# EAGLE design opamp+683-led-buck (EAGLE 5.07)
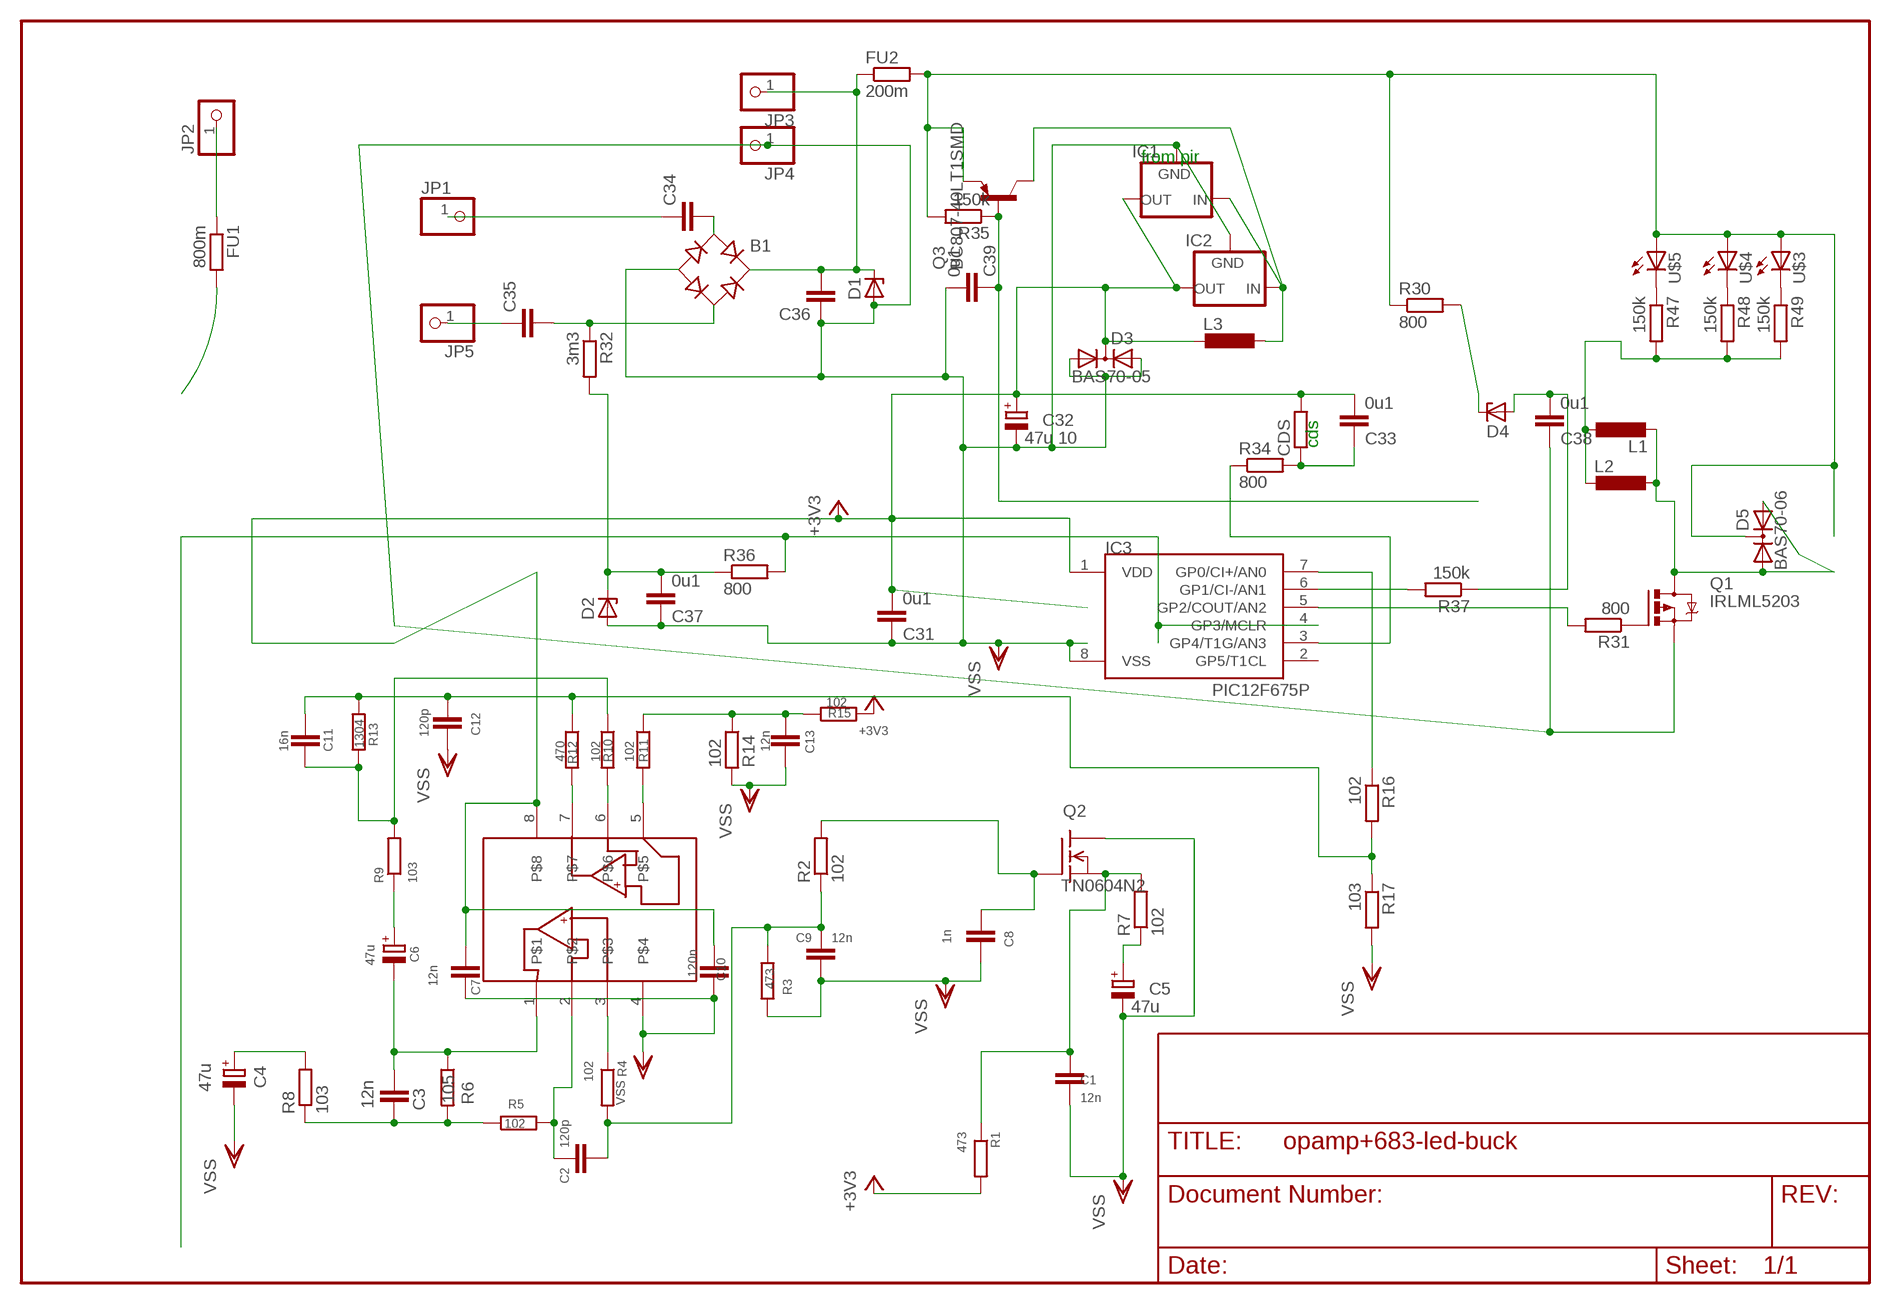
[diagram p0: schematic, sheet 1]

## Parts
B1  RB1A  [RB1A]
C1  12n  C-EUC0805  [C0805]
C2  120p  C-EUC0805  [C0805]
C3  12n  C-EUC0805  [C0805]
C4  47u  CPOL-EUE2.5-5  [E2,5-5]
C5  47u  CPOL-EUE2.5-5  [E2,5-5]
C6  47u  CPOL-EUE2.5-5  [E2,5-5]
C7  12n  C-EUC0805  [C0805]
C8  1n  C-EUC0805  [C0805]
C9  12n  C-EUC0805  [C0805]
C10  120n  C-EUC0805  [C0805]
C11  16n  C-EUC0805  [C0805]
C12  120p  C-EUC0805  [C0805]
C13  12n  C-EUC0805  [C0805]
C31  0u1  C-EUC1206  [C1206]
C32  47u 10  CPOL-EUE2.5-5  [E2,5-5]
C33  0u1  C-EUC1206  [C1206]
C34  C-EU050-025X075  [C050-025X075]
C35  C-EU050-025X075  [C050-025X075]
C36  C-EU050-025X075  [C050-025X075]
C37  0u1  C-EUC0805  [C0805]
C38  0u1  C-EUC0805  [C0805]
C39  0u1  C-EUC1206  [C1206]
CDS  R-EU_0207/5V  [0207/5V]
D1  ZENER-DIODEZD-7.5  [ZDIO-7.5]
D2  ZENER-DIODESOT23  [SOT23]
D3  BAS70-05  [SOT23]
D4  ZENER-DIODESOT23  [SOT23]
D5  BAS70-06  [SOT23]
FU1  800m  R-EU_0204/5  [0204/5]
FU2  200m  R-EU_0204/5  [0204/5]
IC1  XC63FPT  [TO92]
IC2  XC63FPP  [SOT89R]
IC3  PIC12F675P  [DIL8]
JP1  PINHD-1X1  [1X01]
JP2  PINHD-1X1  [1X01]
JP3  PINHD-1X1  [1X01]
JP4  PINHD-1X1  [1X01]
JP5  PINHD-1X1  [1X01]
L1  L-EUL5650M  [L5650M]
L2  L-EU0207/7  [0207/7]
L3  L-EU0204V  [0204V]
Q1  IRLML5203  [MICRO3]
Q2  TN0604N2  [TO-39]
Q3  BC807-40LT1SMD  [SOT23-BEC]
R1  473  R-EU_R0805  [R0805]
R2  102  R-EU_R0805  [R0805]
R3  473  R-EU_R0805  [R0805]
R4  102  R-EU_R0805  [R0805]
R5  102  R-EU_R0805  [R0805]
R6  105  R-EU_R0805  [R0805]
R7  102  R-EU_R0805  [R0805]
R8  103  R-EU_R0805  [R0805]
R9  103  R-EU_R0805  [R0805]
R10  102  R-EU_R0805  [R0805]
R11  102  R-EU_R0805  [R0805]
R12  470  R-EU_R0805  [R0805]
R13  1304  R-EU_R0805  [R0805]
R14  102  R-EU_R0805  [R0805]
R15  102  R-EU_R0805  [R0805]
R16  102  R-EU_R0805  [R0805]
R17  103  R-EU_R1206  [R1206]
R30  800  R-EU_R0805  [R0805]
R31  800  R-EU_R0805  [R0805]
R32  3m3  R-EU_R1206  [R1206]
R34  800  R-EU_0617/22  [0617/22]
R35  150k  R-EU_R0805  [R0805]
R36  800  R-EU_R0805  [R0805]
R37  150k  R-EU_0207/12  [0207/12]
R47  150k  R-EU_R1206  [R1206]
R48  150k  R-EU_R1206  [R1206]
R49  150k  R-EU_R1206  [R1206]
U$1  MCP6042SOIC  [SO-08]
U$3  LED5MM  [LED5MM]
U$4  LED5MM  [LED5MM]
U$5  LED5MM  [LED5MM]

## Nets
+3V3: C7.1 C10.1 C31.2 C32.+ C33.2 CDS.2 D3.3(C) IC1.3(OUT) IC2.3(OUT) IC3.1(VDD) L3.2 R1.2 R15.2 U$1.8
N$1: B1.+ C36.2 D1.C FU2.1 JP3.1
N$4: FU1.1 JP2.1
N$6: D4.3(C) R30.2
N$7: D5.3(C) FU2.2 Q3.E R30.1 R35.2 U$3.A U$4.A U$5.A
N$8: C39.1 Q3.B R35.1
N$9: FU1.2
N$10: Q1.1(G) R31.1
N$11: C5.+ R7.1
N$12: IC3.4(GP3/MCLR) R36.2
N$13: IC3.6(GP1/CI-/AN1) R37.2
N$14: IC3.5(GP2/COUT/AN2) R31.2
N$15: IC1.2(IN) IC2.2(IN) L3.1 Q3.C
N$16: C37.2 D2.3(C) R32.2 R36.1
N$17: C35.1 JP5.1
N$18: B1.AC2 C35.2 R32.1
N$19: R4.1 U$1.3
N$20: C34.1 JP1.1
N$21: IC3.3(GP4/T1G/AN3) R34.1
N$22: L1.1 L2.2 R47.2 R48.2 R49.2
N$23: C33.1 CDS.1 R34.2
N$24: C2.1 R5.2 U$1.2
N$25: C3.2 R5.1 R6.2 R8.1
N$26: D5.1(A1) D5.2(A2) L1.2 L2.1 Q1.3(D)
N$27: C4.+ R8.2
N$28: C11.2 R9.2 R10.1 R13.2
N$29: IC3.7(GP0/CI+/AN0) R16.1
N$30: C3.1 C6.- R6.1 U$1.1
N$31: R10.2 U$1.6
N$32: C11.1 C12.2 R12.1 R13.1 R16.2 R17.1
N$33: B1.AC1 C34.2
N$34: C38.2 D4.1(A) R37.1
N$35: C6.+ R9.1
N$36: R12.2 U$1.7
N$38: R47.1 U$5.K(C)
N$39: R11.2 U$1.5
N$40: C13.1 R11.1 R14.1 R15.1
N$42: C1.1 Q2.1(S) R1.1 R7.2
N$46: C8.1 Q2.2(G) R2.2
N$52: C2.2 C9.1 R2.1 R3.1 R4.2
N$54: R48.1 U$4.K(C)
N$55: R49.1 U$3.K(C)
VSS: B1.- C1.2 C4.- C5.- C7.2 C8.2 C9.2 C10.2 C12.1 C13.2 C31.1 C32.- C36.1 C37.1 C38.1 C39.2 D1.A D2.1(A) D3.1(A1) D3.2(A2) IC1.1(GND) IC2.1(GND) IC3.8(VSS) JP4.1 Q1.2(S) Q2.3(D) R3.2 R14.2 R17.2 U$1.4
Unconnected: IC3.2(GP5/T1CL)

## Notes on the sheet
- from pir
- cds

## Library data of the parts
B1 = rectifier:RB1A: RECTIFIER 1 A
C1-C3 C7-C13 = rcl-2:C-EU: CAPACITOR, European symbol
C4-C6 C32 = rcl:CPOL-EU: POLARIZED CAPACITOR, European symbol
C31 C33-C39 = rcl:C-EU: CAPACITOR, European symbol
CDS = rcl(2):R-EU_: RESISTOR, European symbol
D1 D2 D4 = diode-1:ZENER-DIODE: Z-Diode
D3 = diode-1:BAS70-05: Silicon Schottky Diodes General-purpose diode for high-speed switching
D5 = diode-1:BAS70-06: Silicon Schottky Diodes General-purpose diode for high-speed switching
FU1 FU2 R30-R32 R34-R37 R47-R49 = rcl:R-EU_: RESISTOR, European symbol
IC1 IC2 = v-reg:XC63FP: Positiv Voltage Regulators www.torex.co.jp/english/product/pro02/pdf/0201_xc62fp.pdf
IC3 = microchip-3:PIC12F6*: uPC nW 1k Program Flash memory 2x Timer Comparator 10b A/D converter/ 4xIN
JP1-JP5 = pinhead:PINHD-1X1: PIN HEADER
L1 = rcl-2:L-EU: INDUCTOR, European symbol
L2 L3 = rcl:L-EU: INDUCTOR, European symbol
Q1 = transistor-power:IRLML5203: HEXFET P-Channel Power MOSFET
Q2 = transistor-fet:TN0604N2: N-Channel Enhancement MOSFET 40V; 4A; 0,85Ohm
Q3 = transistor-pnp:BC807*: PNP Transistror
R1-R17 = rcl-2:R-EU_: RESISTOR, European symbol
U$1 = microchip-3:MCP6042
U$3-U$5 = led(3):LED: LED

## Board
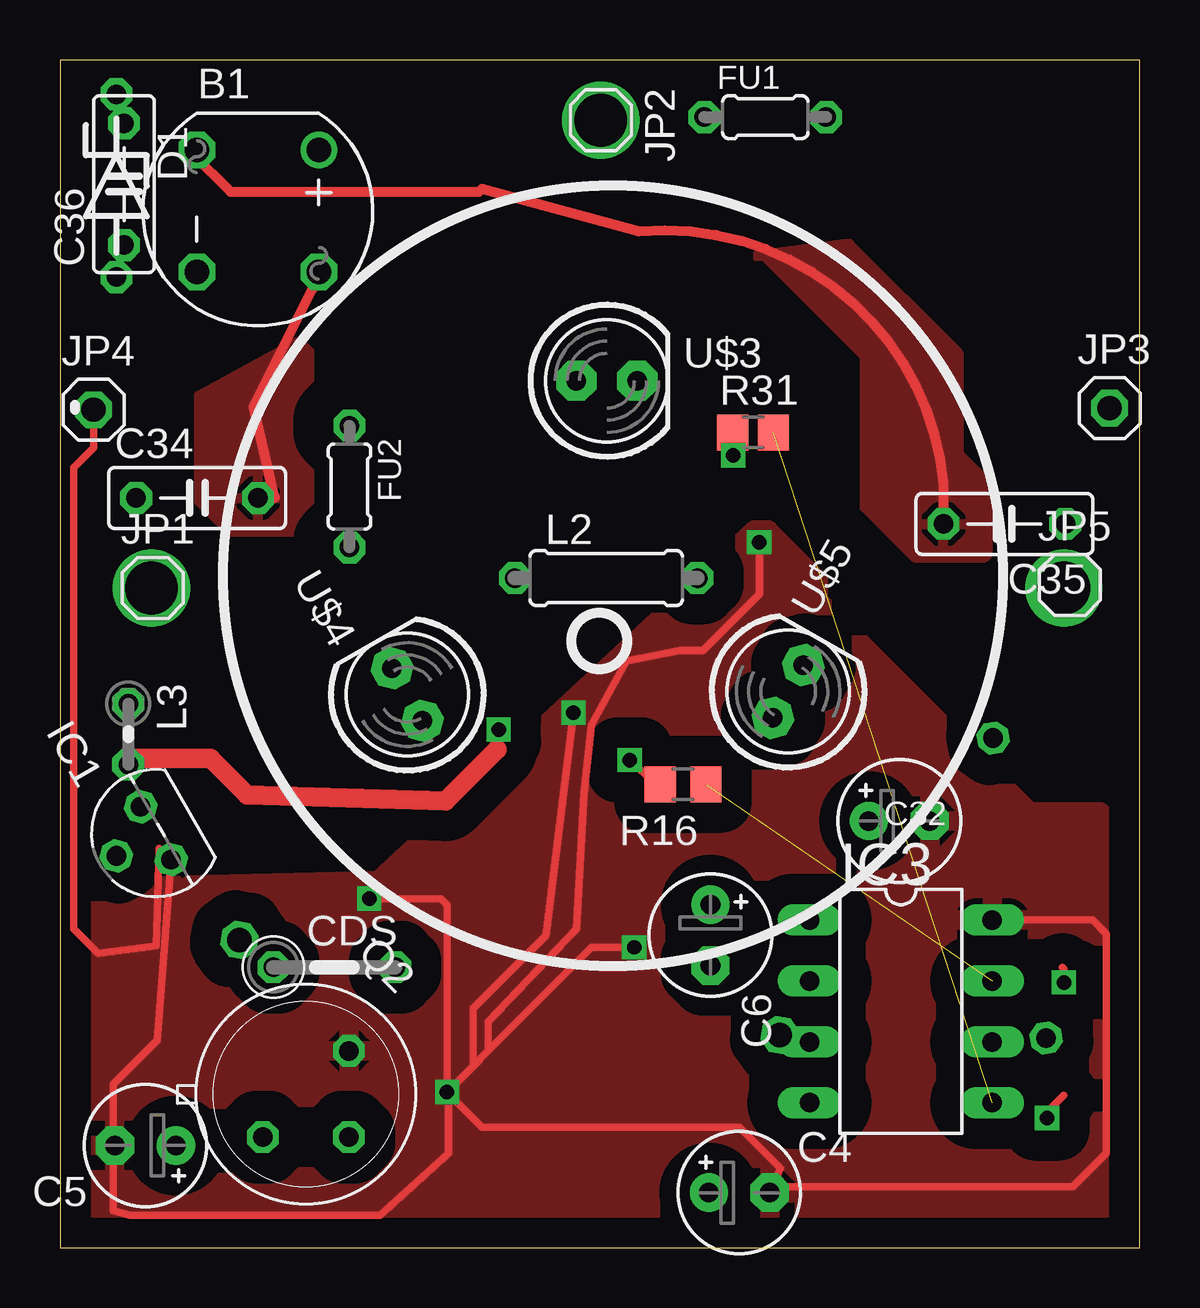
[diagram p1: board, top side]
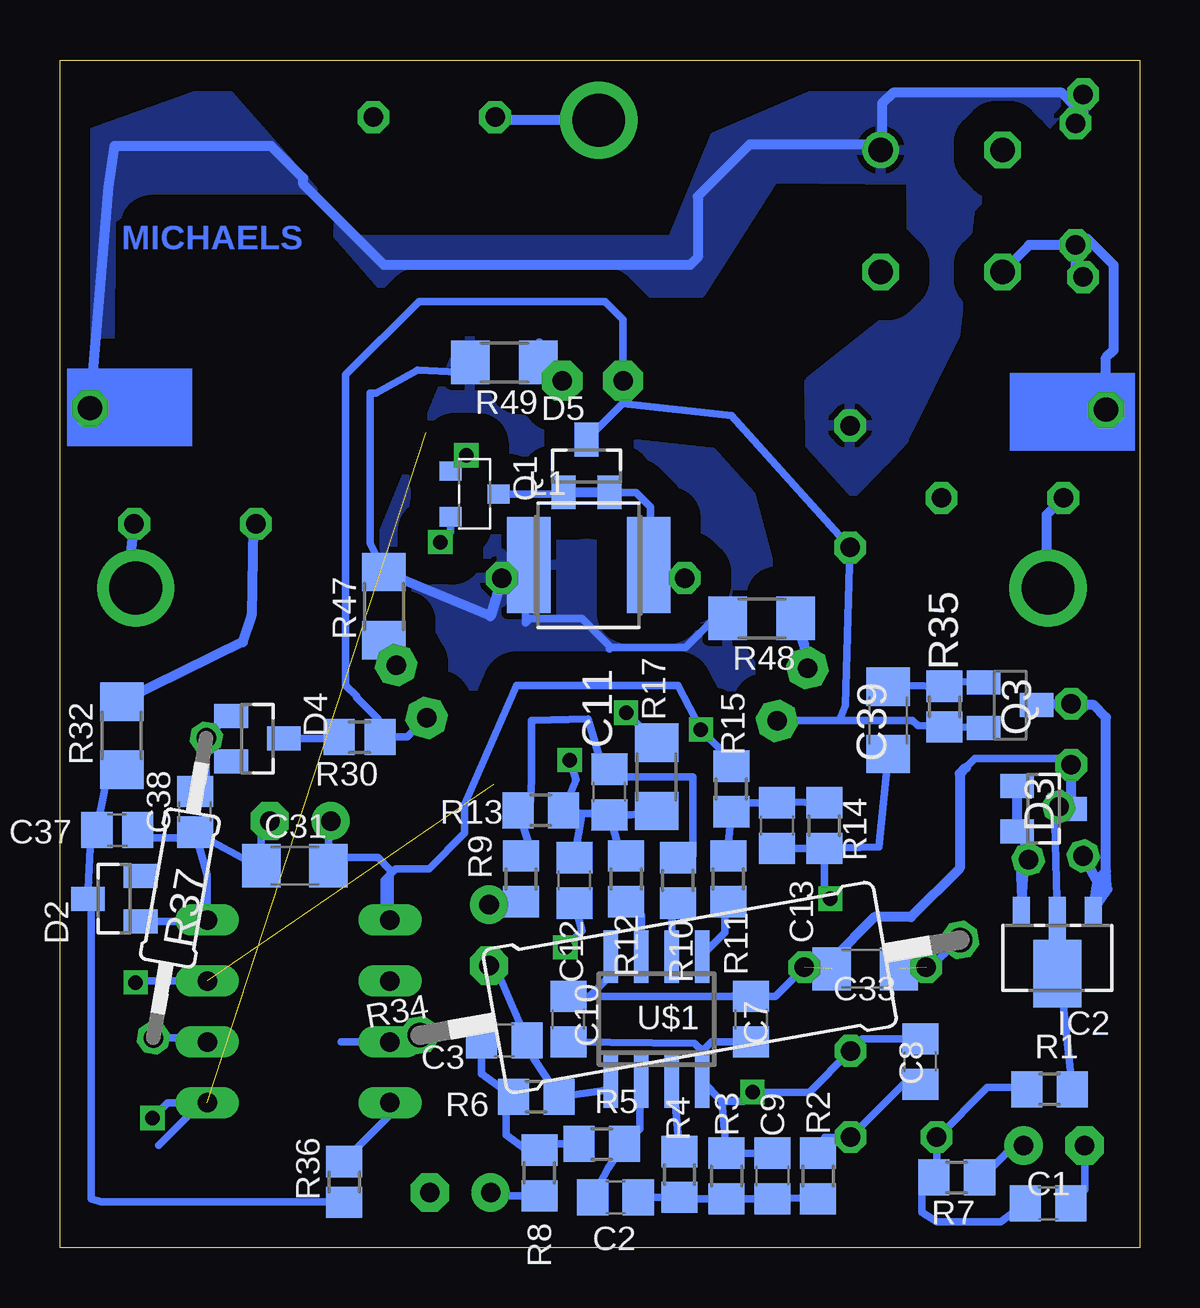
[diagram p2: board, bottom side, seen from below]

Size 45 x 49.5 mm. Coordinates in mm from the lower left corner, seen from the top.
Outline: 0,0 45,0 45,49.5 0,49.5 0,0
Copper layers (1*16): Top 0.035mm / dielectric 1.5mm / Bottom 0.035mm
Design rules "default": minimum track width 10mil, minimum drill 24mil, track to track 8mil, track to pad 8mil, pad to pad 8mil, via to via 8mil, smd to smd 8mil, copper to edge 40mil, drill to drill 8mil, minimum pad ring 10mil, minimum via ring 8mil, stop-mask expansion 4mil, vias tented up to drill 0mil, thermal gap 10mil

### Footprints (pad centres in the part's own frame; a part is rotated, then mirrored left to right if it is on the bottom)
RB1A = drill 1.016 round: + -2.54,2.54 | drill 1.016 octagon: - 2.54,-2.54; AC1 2.54,2.54; AC2 -2.54,-2.54
C0805 = smd 1.3 x 1.5: 1 -0.95,0; 2 0.95,0
E2,5-5 = drill 0.813 pad 1.6 round: + -1.27,0 | drill 0.813 pad 1.6 octagon: - 1.27,0
C1206 = smd 1.6 x 1.8: 1 -1.4,0; 2 1.4,0
C050-025X075 = drill 0.813 octagon: 1 -2.54,0; 2 2.54,0
C0805' = smd 1.3 x 1.5: 1 -0.85,0; 2 0.85,0
0207/5V = drill 0.813 octagon: 1 -2.54,0; 2 2.54,0
ZDIO-7.5 = drill 0.813 octagon: A 3.81,0; C -3.81,0
SOT23 = smd 1 x 1.4: 1 -0.95,-1.1; 2 0.95,-1.1; 3 0,1.1
0204/5 = drill 0.813 octagon: 1 -2.54,0; 2 2.54,0
TO92 = drill 0.813 octagon: 1 -1.27,0; 2 0,1.905; 3 1.27,0
SOT89R = smd 0.7 x 1.1: 1 1.5,-1.75; 2 -1.5,-1.75 | smd 0.7 x 1.8: 3 0,-1.4 | smd 2 x 2.8: 4 0,0.9
DIL8 = drill 0.813 long: 1 -3.81,-3.81; 2 -1.27,-3.81; 3 1.27,-3.81; 4 3.81,-3.81; 5 3.81,3.81; 6 1.27,3.81; 7 -1.27,3.81; 8 -3.81,3.81
1X01 = drill 1.016 octagon: 1 0,0
L5650M = smd 1.8 x 4: 1 -2.5,0; 2 2.5,0
0207/7 = drill 0.813 octagon: 1 -3.81,0; 2 3.81,0
0204V = drill 0.813 octagon: 1 -1.27,0; 2 1.27,0
MICRO3 = smd 0.8 x 0.9: 1 -0.95,-1; 2 0.95,-1; 3 0,1
TO-39 = drill 0.813 octagon: 1 0,-2.54; 2 2.54,0; 3 0,2.54
SOT23-BEC = smd 1 x 1.4: B -0.95,-1.1; C 0,1.1; E 0.95,-1.1
R0805 = smd 1.3 x 1.5: 1 -0.95,0; 2 0.95,0
R1206 = smd 1.6 x 1.803: 1 -1.422,0; 2 1.422,0
R0805' = smd 1.3 x 1.5: 1 -0.85,0; 2 0.85,0
0617/22 = drill 1.016 octagon: 1 -11.43,0; 2 11.43,0
0207/12 = drill 0.813 octagon: 1 -6.35,0; 2 6.35,0
SO-08 = smd 0.6 x 2.2: 1 -1.905,-2.6; 2 -0.635,-2.6; 3 0.635,-2.6; 4 1.905,-2.6; 5 1.905,2.6; 6 0.635,2.6; 7 -0.635,2.6; 8 -1.905,2.6
LED5MM = drill 0.813 pad 1.676 octagon: A -1.27,0; K 1.27,0

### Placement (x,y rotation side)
B1  8.25,43.21 270 top
C1  3.81,1.84 0 bottom
C2  21.84,2.1 0 bottom
C3  26.48,8.64 180 bottom
C4  28.32,2.29 0 top
C5  3.56,4.25 180 top
C6  27.11,13.02 270 top
C7  16.19,9.53 270 bottom
C8  9.14,7.75 90 bottom
C9  15.3,2.98 90 bottom
C10  23.81,9.53 270 bottom
C11  22.1,18.99 90 bottom
C12  23.56,15.3 90 bottom
C13  15.11,17.59 270 bottom
C31  35.21,15.92 0 bottom
C32  34.99,17.78 0 top
C33  11.43,11.62 180 bottom
C34  5.71,31.24 0 top
C35  39.37,30.16 180 top
C36  2.67,44.32 90 top
C37  0u1  [C0805']  42.61,17.4 180 bottom
C38  0u1  [C0805']  39.37,18.16 90 bottom
C39  10.48,21.97 270 bottom
CDS  11.43,11.68 0 top
D1  2.35,44.26 270 top
D2  42.74,14.54 90 bottom
D3  4,18.29 270 bottom
D4  36.77,21.21 270 bottom
D5  23.05,32.58 0 bottom
FU1  29.4,47.12 0 top
FU2  12.07,31.72 270 top
IC1  4,17.28 120 top
IC2  3.43,12.32 180 bottom
IC3  35.05,9.84 270 top
JP1  3.87,27.5 0 top
JP2  22.54,46.99 270 top
JP3  43.75,34.99 0 top
JP4  1.4,34.92 0 top
JP5  42.1,27.62 0 top
L1  22.96,28.44 0 bottom
L2  22.77,27.91 0 top
L3  2.85,21.4 270 top
Q1  27.72,31.41 270 bottom
Q2  10.25,6.4 315 top
Q3  5.4,22.61 270 bottom
R1  3.75,6.6 0 bottom
R2  13.4,2.98 90 bottom
R3  17.21,2.98 90 bottom
R4  19.18,3.05 270 bottom
R5  22.42,4.32 0 bottom
R6  25.15,6.29 180 bottom
R7  7.62,2.92 180 bottom
R8  25.02,3.11 270 bottom
R9  25.78,15.37 90 bottom
R10  19.24,15.3 270 bottom
R11  17.14,15.37 270 bottom
R12  21.4,15.37 270 bottom
R13  24.96,18.22 180 bottom
R14  13.14,17.59 270 bottom
R15  17.02,19.11 90 bottom
R16  25.97,19.3 180 top
R17  20.13,19.62 90 bottom
R30  800  [R0805']  32.51,21.27 180 bottom
R31  800  [R0805']  28.89,33.97 0 top
R32  42.42,21.34 270 bottom
R34  18.74,10.84 10 bottom
R35  150k  [R0805']  8.13,22.54 270 bottom
R36  800  [R0805']  33.15,2.73 90 bottom
R37  40.01,14.99 260 bottom
R47  31.5,26.73 90 bottom
R48  15.75,26.23 180 bottom
R49  26.48,36.89 180 bottom
U$1  20.13,9.53 0 bottom
U$3  22.8,36.13 0 top
U$4  14.48,23.05 120 top
U$5  30.35,23.18 60 top

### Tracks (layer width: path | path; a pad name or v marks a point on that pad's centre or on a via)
+3V3  (via drill 0.6)  (1 unrouted)
  Top 0.305: 18.22,20.77 v18.29,21.59 | L3.2 3.1,20.38
  Top 0.813: 18.22,20.77 16.07,18.61 7.81,18.86 6.29,20.38 3.1,20.38
  Bottom 0.305: 22.92,10.47 C7.1 15.18,10.47 CDS.2 | 22.92,10.47 C10.1 | U$1.8 22.04,11.36 22.92,10.47 | 7.24,20 6.86,20.38 3.1,20.38 L3.2 | C32.+ 33.81,17.69 C31.2 33.47,16.26 31.75,16.26 31.24,15.75 IC3.1 31.5,13.91 31.5,15.3 31.01,15.79 29.62,15.79 28.13,17.27 28.13,18.48 25.97,23.43 19.24,23.43 v18.29,21.59 17.53,20.83 R15.2 | R1.2 3.43,12.45 IC2.3 3.56,18.48 | 3.56,18.48 2.98,18.56 IC1.3 | D3.3 2.92,18.29 3.56,18.48
  Bottom 0.406: L3.2 2.85,18.09 D3.3 | C33.2 12.83,12 11.05,13.78 9.53,13.78 7.49,15.81 7.49,19.75 7.24,20
N$1
  Bottom 0.406: JP3.1 42.99,44.2 42.74,45.91 36.2,45.91 34.86,44.58 34.86,44.32 31.5,40.96 18.73,40.96 18.41,41.27 18.41,43.81 16.26,45.97 11.2,45.97 B1.+ 10.73,45.8 10.73,47.69 10.29,48.13 3.24,48.13 2.67,47.56 C36.2 2.35,47.18 D1.C
  pour Bottom (isolate 1.27, rank 2): 1.52,49.34 9.97,49.59 17.72,46.29 19.49,42 32.64,42 38.29,48.39 44.89,46.04 44.7,36.96 42.93,37.08 42.86,42.86 41.4,43.81 34.86,43.88 31.31,39.8 18.29,39.8 15.24,44.58 9.53,44.51 9.46,39.5 13.78,36.07 13.65,29.65 10.67,32.77 9.84,33.66 7.68,38.04 7.05,43.31
N$2  (via drill 2.2)
  other vias: 3.81,27.5
N$3  (via drill 2.2)
  other vias: 41.85,27.5
N$4
  Bottom 0.406: JP2.1 26.73,46.99 FU1.1
N$5  (via drill 2.2)
  other vias: 22.54,46.99
N$6
  Bottom 0.305: D4.3 33.42,21.21 R30.2
N$7
  Bottom 0.305: 12.51,21.97 9.46,21.97 9.25,21.76 R35.2 8.47,21.72 Q3.E | 12.51,21.97 15.09,21.97 U$4.A | U$5.A 30.52,21.27 R30.1 31.75,21.36 31.75,22.04 32.64,22.92 32.64,22.99 33.08,23.43 33.08,36.39 30.04,39.43 22.29,39.43 21.53,38.67 U$3.A | U$3.A 21.53,35.2 D5.3 | U$3.A 21.53,35.18 17.02,34.67 12.16,29.27 FU2.2 12.26,22.6 12.51,21.97
N$8
  Bottom 0.305: Q3.B 8.35,23.62 R35.1 10.58,23.46 C39.1
N$10  (via drill 0.6)
  Top 0.305: v28.06,33.02 R31.1
  Bottom 0.305: Q1.1 v28.06,33.02
N$11
  Bottom 0.305: R7.1 6.92,2.54 5.33,4.13 4.95,4.13 C5.+
N$12
  Bottom 0.305: IC3.4 31.24,5.52 32.7,4.06 32.7,4.03 R36.2
N$13
  Bottom 0.305: R37.2 39.02,8.73 IC3.6
N$14  (via drill 0.6)  (1 unrouted)
  Top 0.305: v41.15,5.4 41.15,5.65 41.85,6.35
  Bottom 0.305: 40.89,4.25 39.12,6.03 IC3.5 40.51,6.03 v41.15,5.4
N$15
  Bottom 0.406: IC1.2 1.58,14.93 1.4,15.49 1.33,14.93 IC2.2 1.74,15.34 1.4,15.68 1.4,22.1 1.91,22.61 2.78,22.61 L3.1 Q3.C
N$16
  Bottom 0.305: R36.1 33.59,1.91 43.31,1.91 43.69,2.03 43.69,14.63 D2.3 43.71,17.09 C37.2 43.01,19.75 R32.2
N$17
  Bottom 0.406: JP5.1 42.1,28.32 C35.1
N$18
  Top 0.406: B1.AC2 5.52,45.6 7.11,44.01 17.46,44.01 17.59,44.13 24.13,42.35 arc-90 36.83,31.81 C35.2
  Bottom 0.406: R32.1 37.38,25.23 37.02,26.35 36.96,30.04 C35.2
  pour Top (isolate 0.61): 29.02,41.34 29.34,41.34 33.53,37.15 33.53,30.86 35.62,28.77 38.54,28.77 38.67,28.89 38.67,31.88 37.47,33.08 37.47,37.27 32.89,41.85
N$19
  Bottom 0.305: U$1.3 19.43,6.92 R4.1
N$20
  Bottom 0.406: JP1.1 3.87,30.54 C34.1
N$21
  Bottom 0.305: 33.27,8.57 IC3.3 29.72,8.57 R34.1
N$22
  Bottom 0.305: R49.2 28.36,36.49 30.1,36.58 31.81,35.62 32.07,35.62 32.07,29.36 R47.2 | R48.2 17.72,26.23 18.92,25.02 22.04,25.02 22.1,24.96 22.1,25.08 23.24,26.23 25.4,26.23 25.59,26.04 25.59,28.31 L1.1
  Bottom 0.406: R47.2 27.05,26.32 L2.2 26.23,28.25 L1.1
  pour Bottom (isolate 1.27, rank 2): 21.97,38.29 28.07,38.23 36.45,17.72 12.57,17.65 17.97,37.97 21.59,38.23
N$23  (1 unrouted)
  Bottom 0.305: R34.2 8.29,12.1 CDS.1
N$24
  Bottom 0.305: U$1.2 20.83,6.92 20.83,4.96 R5.2 22.16,3.3 C2.1
N$25
  Bottom 0.305: R5.1 24.76,4.32 R8.1 25.52,4.06 26.42,4.7 26.42,5.78 R6.2 27.43,7.24 C3.2
N$26
  Bottom 0.305: Q1.3 24.07,31.41 D5.1 | D5.2 21,31.48 20.38,30.86 20.38,28.51 L1.2
  Bottom 0.406: D5.2 D5.1 | L2.1 20.18,27.91 L1.2
N$27
  Bottom 0.305: R8.2 27.05,2.16 C4.+
N$28
  Bottom 0.305: R10.1 18.61,16.32 18.61,19.62 21.33,19.62 C11.2 22.35,19.87 22.99,22.04 25.34,21.97 25.34,19.49 25.4,18.35 R13.2 25.4,16.7 R9.2
N$29  (via drill 0.6)  (1 unrouted)
  Top 0.305: v41.85,11.05 41.85,11.62 41.78,11.68
  Bottom 0.305: 41.59,11.18 41.53,11.11 IC3.7 41.78,11.11 v41.85,11.05
N$30
  Bottom 0.305: U$1.1 22.29,6.54 R6.1 25.28,7.94 C3.1 26.67,11.31 C6.-
N$31
  Bottom 0.305: U$1.6 19.49,14.23 R10.2
N$32  (via drill 0.6)
  Top 0.305: v23.75,20.32 24.39,19.75 R16.2
  Bottom 0.305: 23.24,18.09 C12.2 | 23.24,18.09 R13.1 23.5,19.5 v23.75,20.32 | 23.24,18.09 21.84,18.09 C11.1 | C11.1 21.72,16.7 R12.1 | R17.1 21.21,18.04 C11.1
N$33
  Top 0.406: C34.2 8.95,31.24 8.06,35.05 10.54,39.96 B1.AC1
  pour Top (isolate 1.676): 5.78,35.5 5.78,31.11 7.05,29.84 9.84,29.84 10.41,30.42 10.41,37.34 9.97,37.78
N$34
  Bottom 0.305: D4.1 37.98,22.16 R37.1 38.9,19.48 C38.2
N$35
  Bottom 0.305: R9.1 26.98,14.42 C6.+
N$36
  Bottom 0.305: U$1.7 20.77,13.85 R12.2
N$38
  Bottom 0.406: U$5.K 31.3,24.7 R47.1
N$39
  Bottom 0.305: U$1.5 18.22,12.19 17.27,13.14 17.27,14.35 R11.2
N$40
  Bottom 0.305: R14.1 15.56,18.6 C13.1 17.34,18.54 R15.1 17.14,16.89 R11.1
N$42
  Bottom 0.305: C1.1 5.78,1.08 8.45,1.08 9.08,1.46 9.08,2.35 R7.2 8.45,2.97 Q2.1 8.41,4.6 6.35,6.67 4.76,6.67 R1.1
N$46
  Bottom 0.305: C8.1 9.85,6.8 Q2.2 13.11,4.6 R2.2
N$52
  Bottom 0.305: R2.1 15.62,2.1 C9.1 R3.1 19.37,2.03 R4.2 21.34,2.1 C2.2
N$54
  Bottom 0.406: U$4.K 13.97,25.11 R48.1
N$55
  Bottom 0.406: U$3.K 25.02,37.69 R49.1
VSS  (via drill 0.6)
  Top 0.305: v23.94,12.51 22.16,12.51 17.84,8.19 | v16.13,6.48 17.59,5.02 28.32,5.02 30.04,3.3 C4.- 30.1,2.54 42.23,2.54 43.62,3.94 43.62,13.08 43.05,13.65 IC3.8 | v16.13,6.48 16.19,6.41 16.19,3.93 13.34,1.33 2.92,1.33 2.22,1.52 2.22,4.19 | 2.22,4.19 2.22,6.79 4.06,8.63 IC1.1 4.32,16.43 4.13,16.64 4,12.57 1.59,12.26 0.57,13.27 0.57,32.51 1.4,33.34 JP4.1 | 2.22,4.19 C5.- | v12.89,14.54 15.88,14.54 16.13,14.29 v16.13,6.48 | v21.4,22.29 20.26,13.02 17.21,9.97 17.21,7.56 | v16.13,6.48 17.21,7.56 | v29.15,29.4 29.15,27.24 26.8,24.89 25.84,24.89 23.62,24.45 22.16,21.78 21.84,18.92 21.53,13.27 17.84,9.4 17.84,8.19 | 17.21,7.56 17.84,8.19
  Bottom 0.305: C7.2 17.84,8.57 18.22,8.19 | 18.22,8.19 18.22,7.62 18.29,7.56 18.29,6.99 U$1.4 17.4,6.1 | C10.2 18.54,8.51 18.22,8.19 | 17.4,6.1 R3.2 C9.2 | C12.1 23.24,13.21 v23.94,12.51 | R14.2 C13.2 | R14.2 10.86,16.7 C39.2 | 17.4,6.1 16.51,6.1 v16.13,6.48 13.77,6.48 Q2.3 11.54,8.7 C8.2 | C5.- 2.29,2.42 C1.2 | R17.2 19.94,20.89 v21.4,22.29 | D2.1 38.92,13.59 IC3.8 38.86,15.53 C38.1 | C38.1 36.68,15.85 C31.1 36.61,17.43 C32.- | C37.1 41.38,17.38 41.27,17.08 39.6,17.08 C38.1 | Q1.2 28.72,29.83 v29.15,29.4 | IC1.1 5.01,15.96 IC2.1 | R14.2 13.14,14.8 v12.89,14.54
  Bottom 0.406: IC2.1 4.74,17.15 D3.2 D3.1 | JP4.1 1.4,37.08 1.08,37.4 1.08,40.96 2.16,42.04 2.41,42.04 C36.1 | C36.1 4.59,41.78 B1.- | C36.1 2.67,41.91 | C36.1 2.67,40.77 D1.A
  pour Top (isolate 1.27): 0,14.99 13.27,15.3 28.96,29.91 29.53,29.91 31.62,27.81 31.62,26.99 40.45,18.16 43.37,18.16 43.81,17.72 43.81,0.76 43.56,0.51 0.76,0.51 0.19,1.08
(copper drawn outside any net)
  shapes: Bottom area x2

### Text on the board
Bottom: MICHAELS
